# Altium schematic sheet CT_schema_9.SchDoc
size 278 x 170 mm
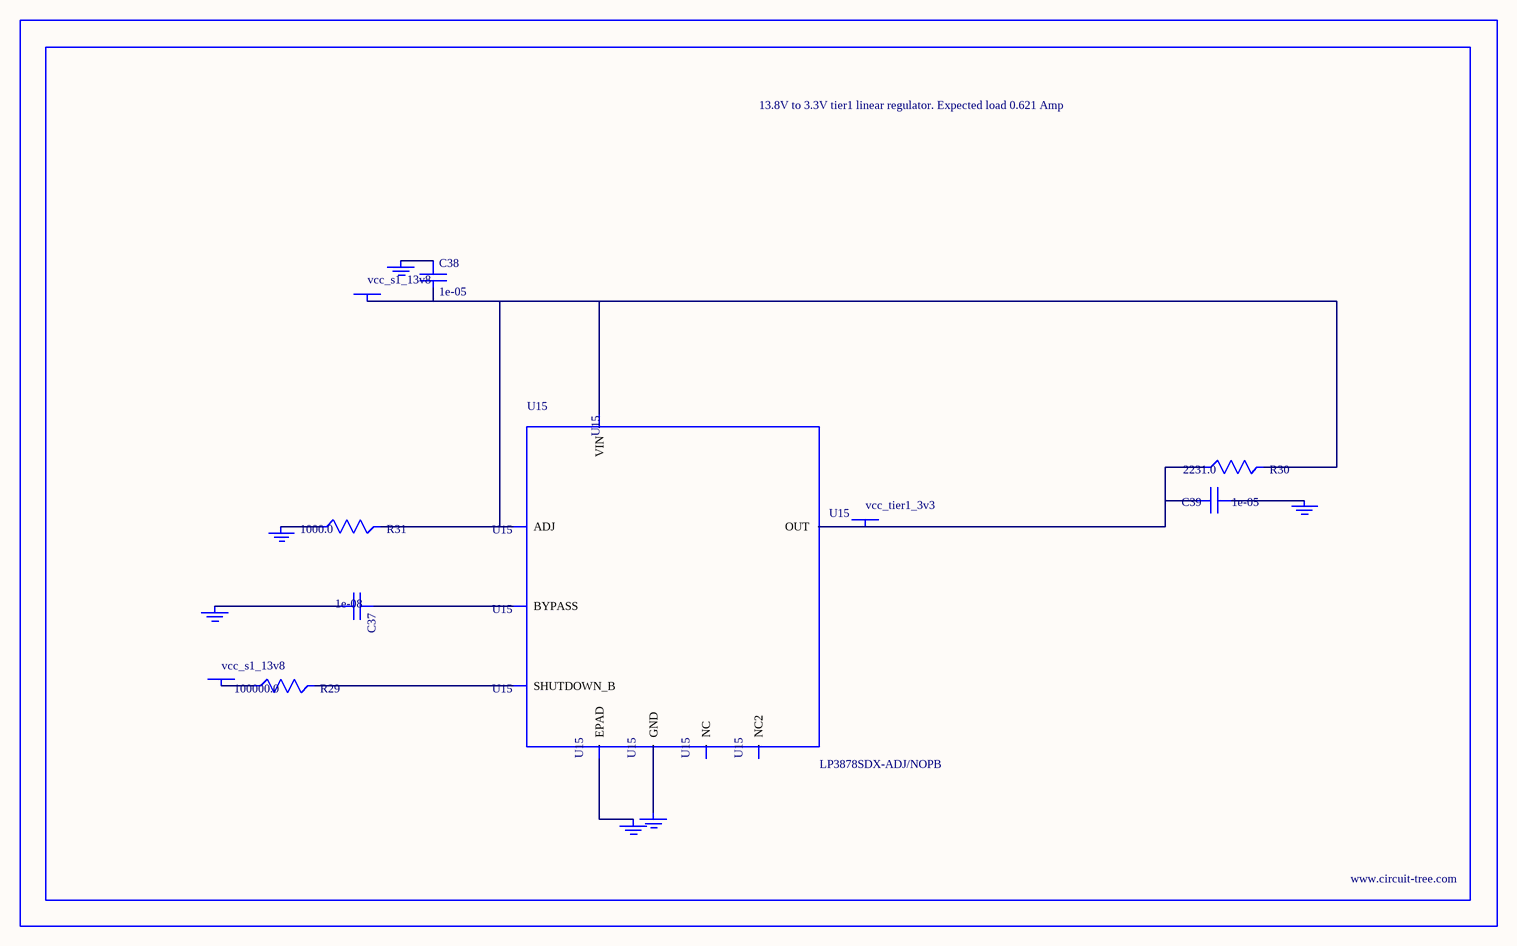
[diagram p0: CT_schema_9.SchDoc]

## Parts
BORDER8  (no value)
C37  1e-08  [C0402]
C38  1e-05  [C1210]
C39  1e-05  [C1210]
GND_INSTANCE_8_0  (no value)
GND_INSTANCE_8_1  (no value)
GND_INSTANCE_8_2  (no value)
GND_INSTANCE_8_3  (no value)
GND_INSTANCE_8_4  (no value)
GND_INSTANCE_8_5  (no value)
POWER_INSTANCE_8_0  vcc_s1_13v8
POWER_INSTANCE_8_1  vcc_s1_13v8
POWER_INSTANCE_8_2  vcc_tier1_3v3
R29  100000.0  [R0603]
R30  2231.0  [R0603]
R31  1000.0  [R0603]
U15  LP3878SDX-ADJ/NOPB  [WSON-8]

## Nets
NetC37_1: C37.1 U15.1(BYPASS)
NetC37_2: C37.2 GND_INSTANCE_8_0.0(GND)
NetC38_1: C38.1 GND_INSTANCE_8_1.0(GND)
NetC38_2: C38.2 POWER_INSTANCE_8_0.0(PWR) R30.2 R31.2 U15.4(VIN) U15.6(ADJ)
NetC39_1: C39.1 GND_INSTANCE_8_2.0(GND)
NetC39_2: C39.2 POWER_INSTANCE_8_2.0(PWR) R30.1 U15.5(OUT)
NetGND_INSTANCE_8_3_0: GND_INSTANCE_8_3.0(GND) R31.1
NetGND_INSTANCE_8_4_0: GND_INSTANCE_8_4.0(GND) U15.PAD(EPAD)
NetGND_INSTANCE_8_5_0: GND_INSTANCE_8_5.0(GND) U15.3(GND)
NetPOWER_INSTANCE_8_1_0: POWER_INSTANCE_8_1.0(PWR) R29.1
NetR29_2: R29.2 U15.8(SHUTDOWN_B)

Not connected (* = marked no-connect by the designer): U15 2(NC) 7(NC2)

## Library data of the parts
BORDER8 = BORDER_PAGE8
C37 = C0402C103K3RAC
C38 = C1210C106K5PACTU
C39 = GRM32DR61E106MA12L
GND_INSTANCE_8_0-GND_INSTANCE_8_5 = GND
POWER_INSTANCE_8_0-POWER_INSTANCE_8_2 = PWR
R29 = RC0603JR-07100KL
R30 = R30
R31 = RC0603JR-071KL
